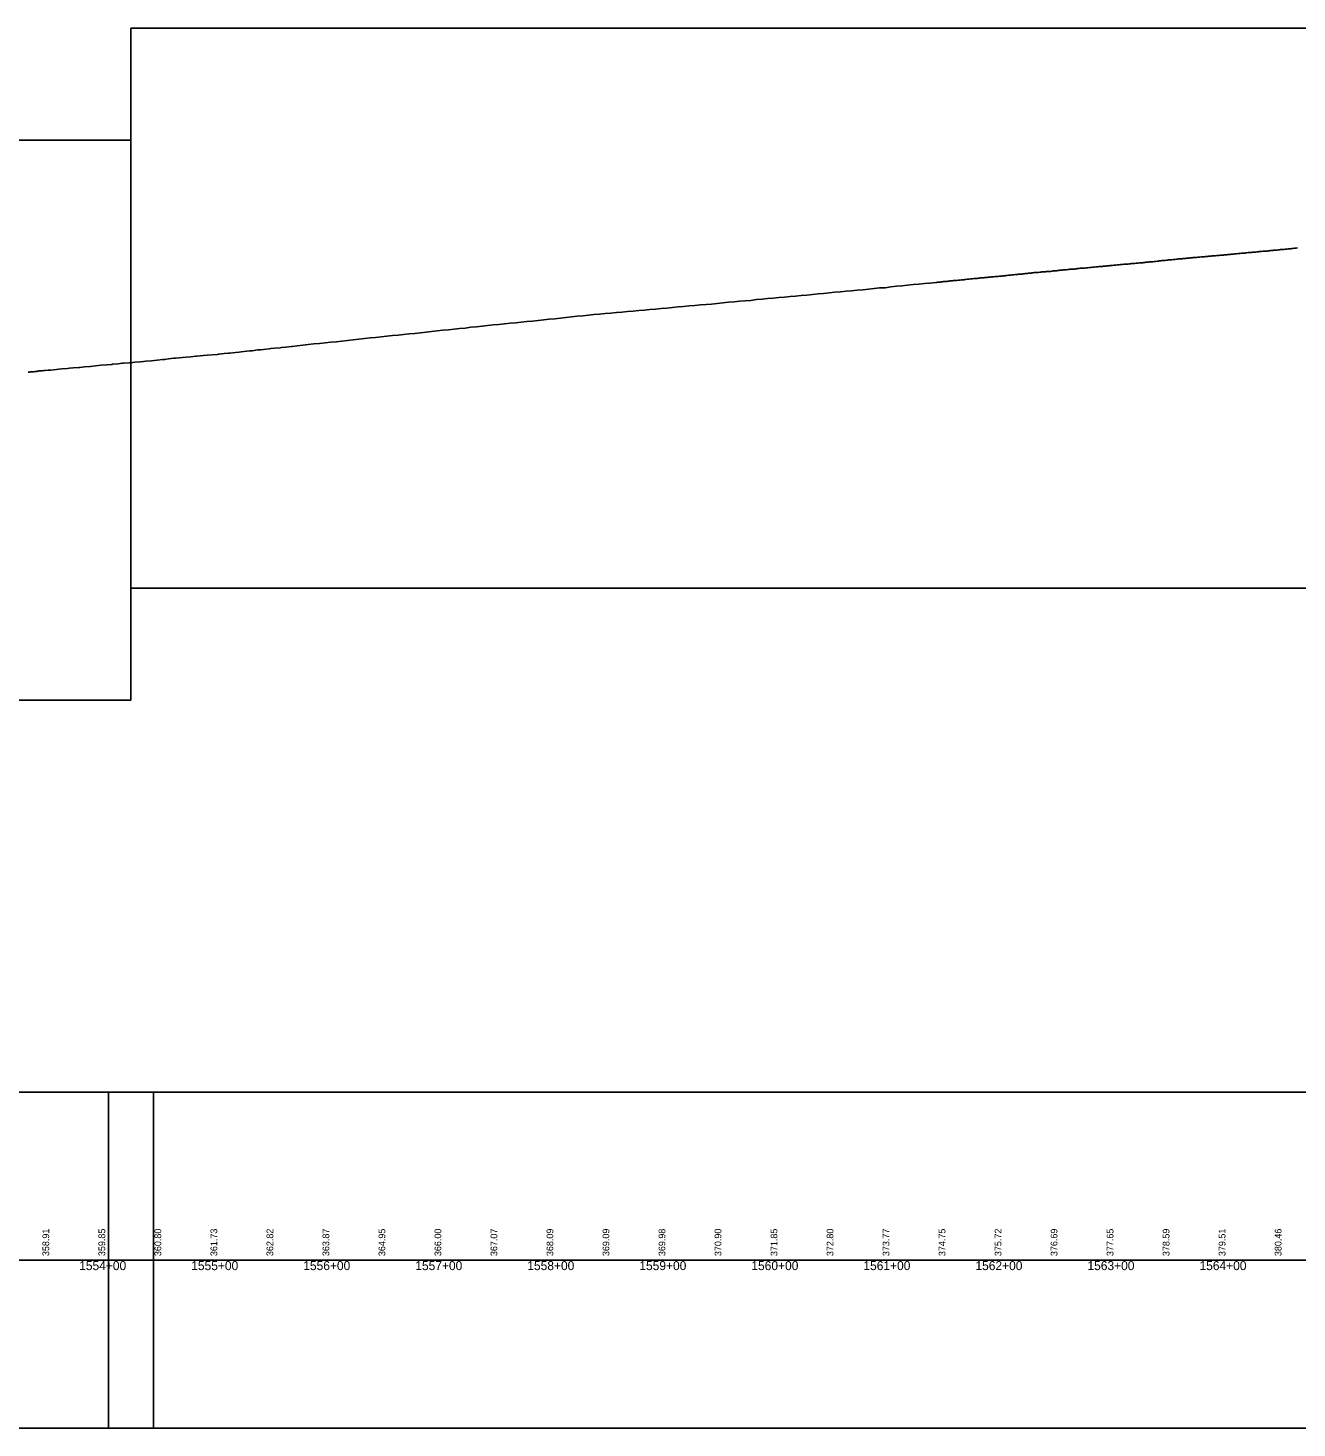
# Model space of a CAD drawing. Extents: x 2898 to 49495, y -15038 to -13538.
# Drawn here: x 44883 to 46016, y -15038 to -13788 of the extents above; entities that cross this region are included whole.
import ezdxf

# ---------------------------------------------------------------- set-up
doc = ezdxf.new("R2010")
doc.units = 0
for name, color, linetype in [('RD_DDB_Profile_EX', 7, 'Continuous'), ('RD_DDB_StaTX', 7, 'Continuous'), ('RD_DDB_StripGrade', 7, 'Continuous'), ('RD_GPK_Profile_Cell', 7, 'Continuous'), ('RD_SHT_ShtClip', 7, 'Continuous')]:
    doc.layers.add(name, color=color, linetype=linetype)

msp = doc.modelspace()

# ---------------------------------------------------------------- linework, layer by layer
at = {"layer": 'RD_DDB_Profile_EX'}
for points in [[(45945.6, -13991.7), (45946.6, -13991.6), (45947.6, -13991.4), (45948.6, -13991.4), (45949.6, -13991.3), (45950.6, -13991.2), (45951.6, -13991.1), (45952.6, -13991), (45953.6, -13990.9), (45954.6, -13990.8), (45955.6, -13990.7), (45956.6, -13990.6), (45957.6, -13990.5), (45958.6, -13990.4), (45959.6, -13990.3), (45960.6, -13990.1), (45961.6, -13990.1), (45962.6, -13990), (45963.6, -13989.9), (45964.6, -13989.8), (45965.6, -13989.7), (45966.6, -13989.6), (45967.6, -13989.5), (45968.6, -13989.4), (45969.6, -13989.4), (45970.6, -13989.2), (45971.6, -13989.1), (45972.6, -13989), (45973.6, -13989), (45974.6, -13988.9), (45975.6, -13988.8), (45976.6, -13988.7), (45977.6, -13988.6), (45978.6, -13988.6), (45979.6, -13988.5), (45980.6, -13988.3), (45981.6, -13988.2), (45982.6, -13988.1), (45983.6, -13988), (45984.6, -13987.9), (45985.6, -13987.8), (45986.6, -13987.8), (45987.6, -13987.7), (45988.6, -13987.6), (45989.6, -13987.6), (45990.6, -13987.4), (45991.6, -13987.3), (45992.6, -13987.2), (45993.6, -13987.1), (45994.6, -13987), (45995.6, -13986.9), (45996.6, -13986.8), (45997.6, -13986.7), (45998.6, -13986.7), (45999.6, -13986.5), (46000.6, -13986.4), (46001.6, -13986.3), (46002.6, -13986.2), (46003.6, -13986.2), (46004.6, -13986.1), (46005.6, -13986), (46006.6, -13985.8), (46007.6, -13985.8), (46008.6, -13985.6), (46009.6, -13985.5), (46010.6, -13985.5), (46011.6, -13985.4), (46012.6, -13985.2), (46013.6, -13985.1), (46014.6, -13985), (46015.6, -13985), (46016.6, -13984.8)], [(45845.6, -14001), (45846.6, -14000.9), (45847.6, -14000.7), (45848.6, -14000.7), (45849.6, -14000.6), (45850.6, -14000.5), (45851.6, -14000.4), (45852.6, -14000.3), (45853.6, -14000.2), (45854.6, -14000.2), (45855.6, -14000), (45856.6, -13999.9), (45857.6, -13999.8), (45858.6, -13999.7), (45859.6, -13999.7), (45860.6, -13999.5), (45861.6, -13999.4), (45862.6, -13999.4), (45863.6, -13999.3), (45864.6, -13999.2), (45865.6, -13999.2), (45866.6, -13999), (45867.6, -13998.9), (45868.6, -13998.8), (45869.6, -13998.7), (45870.6, -13998.7), (45871.6, -13998.6), (45872.6, -13998.5), (45873.6, -13998.4), (45874.6, -13998.3), (45875.6, -13998.2), (45876.6, -13998.1), (45877.6, -13998), (45878.6, -13998), (45879.6, -13997.8), (45880.6, -13997.7), (45881.6, -13997.6), (45882.6, -13997.6), (45883.6, -13997.4), (45884.6, -13997.3), (45885.6, -13997.2), (45886.6, -13997.2), (45887.6, -13997.1), (45888.6, -13997), (45889.6, -13997), (45890.6, -13996.8), (45891.6, -13996.6), (45892.6, -13996.6), (45893.6, -13996.5), (45894.6, -13996.4), (45895.6, -13996.2), (45896.6, -13996.1), (45897.6, -13996.1), (45898.6, -13996), (45899.6, -13995.8), (45900.6, -13995.8), (45901.6, -13995.6), (45902.6, -13995.6), (45903.6, -13995.5), (45904.6, -13995.4), (45905.6, -13995.2), (45906.6, -13995.1), (45907.6, -13995.1), (45908.6, -13994.9), (45909.6, -13994.8), (45910.6, -13994.7), (45911.6, -13994.7), (45912.6, -13994.6), (45913.6, -13994.5), (45914.6, -13994.4), (45915.6, -13994.3), (45916.6, -13994.2), (45917.6, -13994.1), (45918.6, -13994), (45919.6, -13993.9), (45920.6, -13993.8), (45921.6, -13993.7), (45922.6, -13993.6), (45923.6, -13993.5), (45924.6, -13993.4), (45925.6, -13993.4), (45926.6, -13993.3), (45927.6, -13993.2), (45928.6, -13993.1), (45929.6, -13993), (45930.6, -13992.9), (45931.6, -13992.9), (45932.6, -13992.8), (45933.6, -13992.7), (45934.6, -13992.5), (45935.6, -13992.4), (45936.6, -13992.4), (45937.6, -13992.3), (45938.6, -13992.3), (45939.6, -13992.1), (45940.6, -13992), (45941.6, -13992), (45942.6, -13991.8), (45943.6, -13991.8), (45944.6, -13991.7), (45945.6, -13991.7)], [(45458.7, -14038.1), (45463.7, -14037.5), (45468.7, -14037.1), (45473.7, -14036.6), (45478.7, -14036.2), (45483.7, -14035.7), (45488.7, -14035.3), (45493.7, -14034.9), (45498.7, -14034.4), (45503.7, -14033.9), (45508.7, -14033.4), (45513.7, -14033), (45518.7, -14032.5), (45523.7, -14032), (45528.7, -14031.7), (45533.7, -14031), (45538.7, -14030.6), (45543.7, -14030.1), (45548.7, -14029.6), (45553.7, -14029.2), (45558.7, -14028.8), (45563.7, -14028.2), (45568.7, -14027.8), (45573.7, -14027.3), (45578.7, -14026.9), (45583.7, -14026.3), (45588.7, -14025.8), (45593.7, -14025.4), (45598.7, -14024.9), (45603.7, -14024.4), (45608.7, -14024.1), (45613.7, -14023.4), (45618.7, -14023.1), (45623.7, -14022.6), (45628.7, -14022.1), (45633.7, -14021.7), (45638.7, -14021.1), (45643.7, -14020.6), (45648.7, -14020.4), (45653.7, -14019.6), (45658.7, -14019.1), (45663.6, -14018.6), (45668.6, -14018.1), (45673.6, -14017.6), (45678.6, -14017.1), (45683.6, -14016.7), (45688.6, -14016.2), (45693.7, -14015.7), (45694.7, -14015.6), (45695.7, -14015.5), (45696, -14015.5), (45696.7, -14015.5), (45697.7, -14015.3), (45698.7, -14015.2), (45699.7, -14015.1), (45700.7, -14014.9), (45701.7, -14014.9), (45702.7, -14014.8), (45703.7, -14014.7), (45704.7, -14014.6), (45705.7, -14014.5), (45706.7, -14014.3), (45707.7, -14014.2), (45708.7, -14014.1), (45709.7, -14014), (45710.7, -14014), (45711.7, -14013.9), (45712.7, -14013.8), (45713.7, -14013.7), (45714.7, -14013.6), (45715.7, -14013.5), (45716.7, -14013.4), (45717.7, -14013.4), (45718.7, -14013.3), (45719.7, -14013.1), (45720.7, -14012.9), (45721.7, -14012.8), (45722.7, -14012.7), (45723.7, -14012.7), (45724.7, -14012.5), (45725.7, -14012.4), (45726.7, -14012.3), (45727.7, -14012.2), (45728.7, -14012.2), (45729.6, -14012), (45730.7, -14012), (45731.7, -14011.9), (45732.7, -14011.8), (45733.7, -14011.6), (45734.6, -14011.5), (45735.7, -14011.5), (45736.7, -14011.4), (45737.7, -14011.3), (45738.7, -14011.2), (45739.6, -14011.1), (45740.7, -14011), (45741.7, -14010.9), (45742.7, -14010.8), (45743.6, -14010.7), (45744.6, -14010.6), (45745.6, -14010.5)], [(45745.6, -14010.5), (45746.7, -14010.4), (45747.7, -14010.3), (45748.6, -14010.2), (45749.6, -14010.2), (45750.6, -14010.1), (45751.7, -14010), (45752.7, -14009.9), (45753.6, -14009.8), (45754.6, -14009.7), (45755.6, -14009.6), (45756.6, -14009.5), (45757.6, -14009.4), (45758.6, -14009.2), (45759.6, -14009.2), (45760.6, -14009.2), (45761.6, -14009), (45762.6, -14008.9), (45763.6, -14008.8), (45764.6, -14008.7), (45765.6, -14008.6), (45766.6, -14008.6), (45767.6, -14008.4), (45768.6, -14008.3), (45769.6, -14008.4), (45770.6, -14008.4), (45771.6, -14008), (45772.6, -14007.9), (45773.6, -14007.8), (45774.6, -14007.7), (45775.6, -14007.6), (45776.6, -14007.5), (45777.6, -14007.4), (45778.6, -14007.3), (45779.6, -14007.2), (45780.6, -14007), (45781.6, -14006.9), (45782.6, -14006.8), (45783.6, -14006.7), (45784.6, -14006.7), (45785.6, -14006.7), (45786.6, -14006.6), (45787.6, -14006.5), (45788.6, -14006.3), (45789.6, -14006.3), (45790.6, -14006.2), (45791.6, -14006.1), (45792.6, -14006), (45793.6, -14005.9), (45794.6, -14005.8), (45795.6, -14005.8), (45796.6, -14005.8), (45797.6, -14005.5), (45798.6, -14005.4), (45799.6, -14005.3), (45800.6, -14005.2), (45801.6, -14005.2), (45802.6, -14005.1), (45803.6, -14005), (45804.6, -14004.8), (45805.6, -14004.7), (45806.6, -14004.6), (45807.6, -14004.5), (45808.6, -14004.4), (45809.6, -14004.4), (45810.6, -14004.3), (45811.6, -14004.1), (45812.6, -14004), (45813.6, -14003.9), (45814.6, -14003.9), (45815.6, -14003.8), (45816.6, -14003.7), (45817.6, -14003.7), (45818.6, -14003.4), (45819.6, -14003.4), (45820.6, -14003.3), (45821.6, -14003.2), (45822.6, -14003), (45823.6, -14002.9), (45824.6, -14003), (45825.6, -14002.8), (45826.6, -14002.8), (45827.6, -14002.7), (45828.6, -14002.6), (45829.6, -14002.5), (45830.6, -14002.4), (45831.6, -14002.3), (45832.6, -14002.2), (45833.6, -14002.1), (45834.6, -14002), (45835.6, -14001.9), (45836.6, -14001.8), (45837.6, -14001.7), (45838.6, -14001.6), (45839.6, -14001.4), (45840.6, -14001.4), (45841.6, -14001.4), (45842.6, -14001.3), (45843.6, -14001.2), (45844.6, -14001.1), (45845.6, -14001)], [(45003.8, -14084.4), (45005.6, -14084.3), (45008.8, -14084), (45013.7, -14083.4), (45015.1, -14083.2), (45024.6, -14082.4), (45028.7, -14082), (45033.4, -14081.6), (45034, -14081.5), (45043.5, -14080.7), (45052.6, -14079.9), (45053, -14079.8), (45053.7, -14079.8), (45058.7, -14079.2), (45062.5, -14078.8), (45063.7, -14078.7), (45068.7, -14078.1), (45071.9, -14077.8), (45073.7, -14077.6), (45078.7, -14077.1), (45081.4, -14076.8), (45083.7, -14076.6), (45088.7, -14075.9), (45090.9, -14075.7), (45093.7, -14075.5), (45098.7, -14074.9), (45100.3, -14074.7), (45103.7, -14074.3), (45108.7, -14073.9), (45109.8, -14073.7), (45113.7, -14073.3), (45118.7, -14072.8), (45119.3, -14072.7), (45123.7, -14072.2), (45128.7, -14071.6), (45133.7, -14071.1), (45138.7, -14070.6), (45143.7, -14070.2), (45148.7, -14069.5), (45153.7, -14069.1), (45158.7, -14068.6), (45163.7, -14068), (45168.8, -14067.5), (45173.8, -14066.9), (45178.8, -14066.4), (45183.8, -14065.8), (45188.8, -14065.2), (45193.8, -14064.7), (45198.8, -14064.2), (45203.8, -14063.7), (45208.8, -14063.1), (45213.8, -14062.6), (45218.8, -14062.1), (45223.8, -14061.5), (45228.8, -14061.3), (45233.8, -14060.5), (45238.8, -14060), (45243.8, -14059.4), (45248.8, -14059), (45253.8, -14058.4), (45258.8, -14058), (45263.8, -14057.5), (45268.8, -14056.9), (45273.8, -14056.4), (45278.8, -14055.7), (45283.8, -14055.2), (45288.8, -14054.6), (45293.8, -14054.1), (45298.8, -14053.6), (45303.8, -14053.1), (45308.8, -14052.6), (45313.8, -14052.1), (45318.8, -14051.6), (45323.8, -14051), (45328.8, -14050.4), (45333.8, -14050.1), (45338.8, -14049.5), (45343.8, -14048.9), (45348.7, -14048.5), (45353.7, -14048), (45358.7, -14047.5), (45363.7, -14046.9), (45368.7, -14046.4), (45373.7, -14045.9), (45378.7, -14045.4), (45383.7, -14044.8), (45388.7, -14044.4), (45393.7, -14043.9), (45398.7, -14043.5), (45403.7, -14043), (45408.7, -14042.5), (45413.7, -14042.1), (45418.7, -14041.6), (45423.7, -14041.2), (45428.7, -14040.7), (45433.7, -14040.3), (45438.7, -14039.9), (45443.7, -14039.4), (45448.7, -14039), (45453.7, -14038.5), (45458.7, -14038.1)], [(44883.5, -14095.8), (44884.5, -14095.7), (44885.5, -14095.6), (44886.5, -14095.5), (44887.5, -14095.4), (44888.5, -14095.4), (44889.5, -14095.2), (44890.5, -14095.1), (44891.5, -14095.1), (44892, -14095), (44892.5, -14094.9), (44893.5, -14094.7), (44894.5, -14094.7), (44895.5, -14094.7), (44896.5, -14094.5), (44897.5, -14094.4), (44898.8, -14094.3), (44901.4, -14094.1), (44903.8, -14093.9), (44908.8, -14093.5), (44910.9, -14093.2), (44913.8, -14092.9), (44918.8, -14092.4), (44920.4, -14092.3), (44923.8, -14092), (44928.8, -14091.6), (44929.9, -14091.5), (44933.8, -14091.1), (44938.8, -14090.6), (44939.3, -14090.6), (44943.8, -14090.1), (44948.8, -14089.6), (44953.8, -14089.2), (44958.3, -14088.8), (44958.8, -14088.7), (44963.8, -14088.3), (44967.7, -14087.8), (44968.8, -14087.7), (44973.8, -14087.4), (44977.2, -14087), (44978.8, -14086.8), (44983.8, -14086.5), (44986.7, -14086.2), (44988.8, -14086), (44993.8, -14085.5), (44996.2, -14085.2), (44998.8, -14084.9), (45003.8, -14084.4)]]:
    msp.add_lwpolyline(points, dxfattribs=at)
at = {"layer": 'RD_GPK_Profile_Cell'}
msp.add_line((2976.1, -14888.5), (48721.1, -14888.5), dxfattribs=at)
at = {"layer": 'RD_SHT_ShtClip'}
for points in [[(44975.4, -13788.5), (44975.4, -14288.5), (46475.4, -14288.5), (46475.4, -14288.5), (46475.4, -13788.5), (46475.4, -13788.5)], [(43475.4, -13888.5), (43475.4, -14388.5), (44975.4, -14388.5), (44975.4, -14388.5), (44975.4, -13888.5), (44975.4, -13888.5)], [(43455.4, -14738.5), (44995.4, -14738.5), (44995.4, -15038.5), (43455.4, -15038.5)], [(44955.4, -14738.5), (46495.4, -14738.5), (46495.4, -15038.5), (44955.4, -15038.5)]]:
    msp.add_lwpolyline(points, close=True, dxfattribs=at)

# ---------------------------------------------------------------- texts
at = {"layer": 'RD_DDB_StaTX'}
for s, p in [('1554+00', (44929.2, -14897.5)), ('1555+00', (45029.2, -14897.5)), ('1556+00', (45129.2, -14897.5)), ('1557+00', (45229.2, -14897.5)), ('1558+00', (45329.2, -14897.5)), ('1559+00', (45429.2, -14897.5)), ('1560+00', (45529.2, -14897.5)), ('1561+00', (45629.2, -14897.5)), ('1562+00', (45729.2, -14897.5)), ('1563+00', (45829.2, -14897.5)), ('1564+00', (45929.2, -14897.5))]:
    msp.add_text(s, height=8, dxfattribs=at).set_placement(p)
at = {"layer": 'RD_DDB_StripGrade'}
for s, p in [('358.91', (44902.4, -14885)), ('359.85', (44952.4, -14885)), ('360.80', (45002.4, -14885)), ('361.73', (45052.4, -14885)), ('362.82', (45102.4, -14885)), ('363.87', (45152.4, -14885)), ('364.95', (45202.4, -14885)), ('366.00', (45252.4, -14885)), ('367.07', (45302.4, -14885)), ('368.09', (45352.4, -14885)), ('369.09', (45402.4, -14885)), ('369.98', (45452.4, -14885)), ('370.90', (45502.4, -14885)), ('371.85', (45552.4, -14885)), ('372.80', (45602.4, -14885)), ('373.77', (45652.4, -14885)), ('374.75', (45702.4, -14885)), ('375.72', (45752.4, -14885)), ('376.69', (45802.4, -14885)), ('377.65', (45852.4, -14885)), ('378.59', (45902.4, -14885)), ('379.51', (45952.4, -14885)), ('380.46', (46002.4, -14885))]:
    msp.add_text(s, height=6, rotation=90, dxfattribs=at).set_placement(p)

doc.saveas('drawing.dxf')
